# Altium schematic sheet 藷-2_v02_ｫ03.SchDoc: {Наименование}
size 420 x 297 mm; DrawnBy: Булычев; Engineer: {Инженер}; DocumentNumber: СИЭТ 21.02.110.000 Э3; SheetNumber: 3; SheetTotal: 6; Title1str: Плата управления; PageSetup: Record=PageOptions|CenterHorizontal=False|CenterVertical=False|PrintScale=0.95|XCorrection=1.00|YCorrection=1.00|PrintKind=2|BorderSize=5000000|LeftOffset=300|BottomOffset=0|Orientation=2|PaperLength=4200|PaperWidth=2970|Scale=100|PaperSource=15|PrintQuality=-1|MediaType=1|DitherType=10|PaperKind=ISO A3|PrintScaleMode=1; Title2str: (ПУ-2); EngineerName: {Инженер}; DocumentType: Схема электрическая принципиальная; DocumentType1str: {Документ}; DocumentType2str: {Документ}
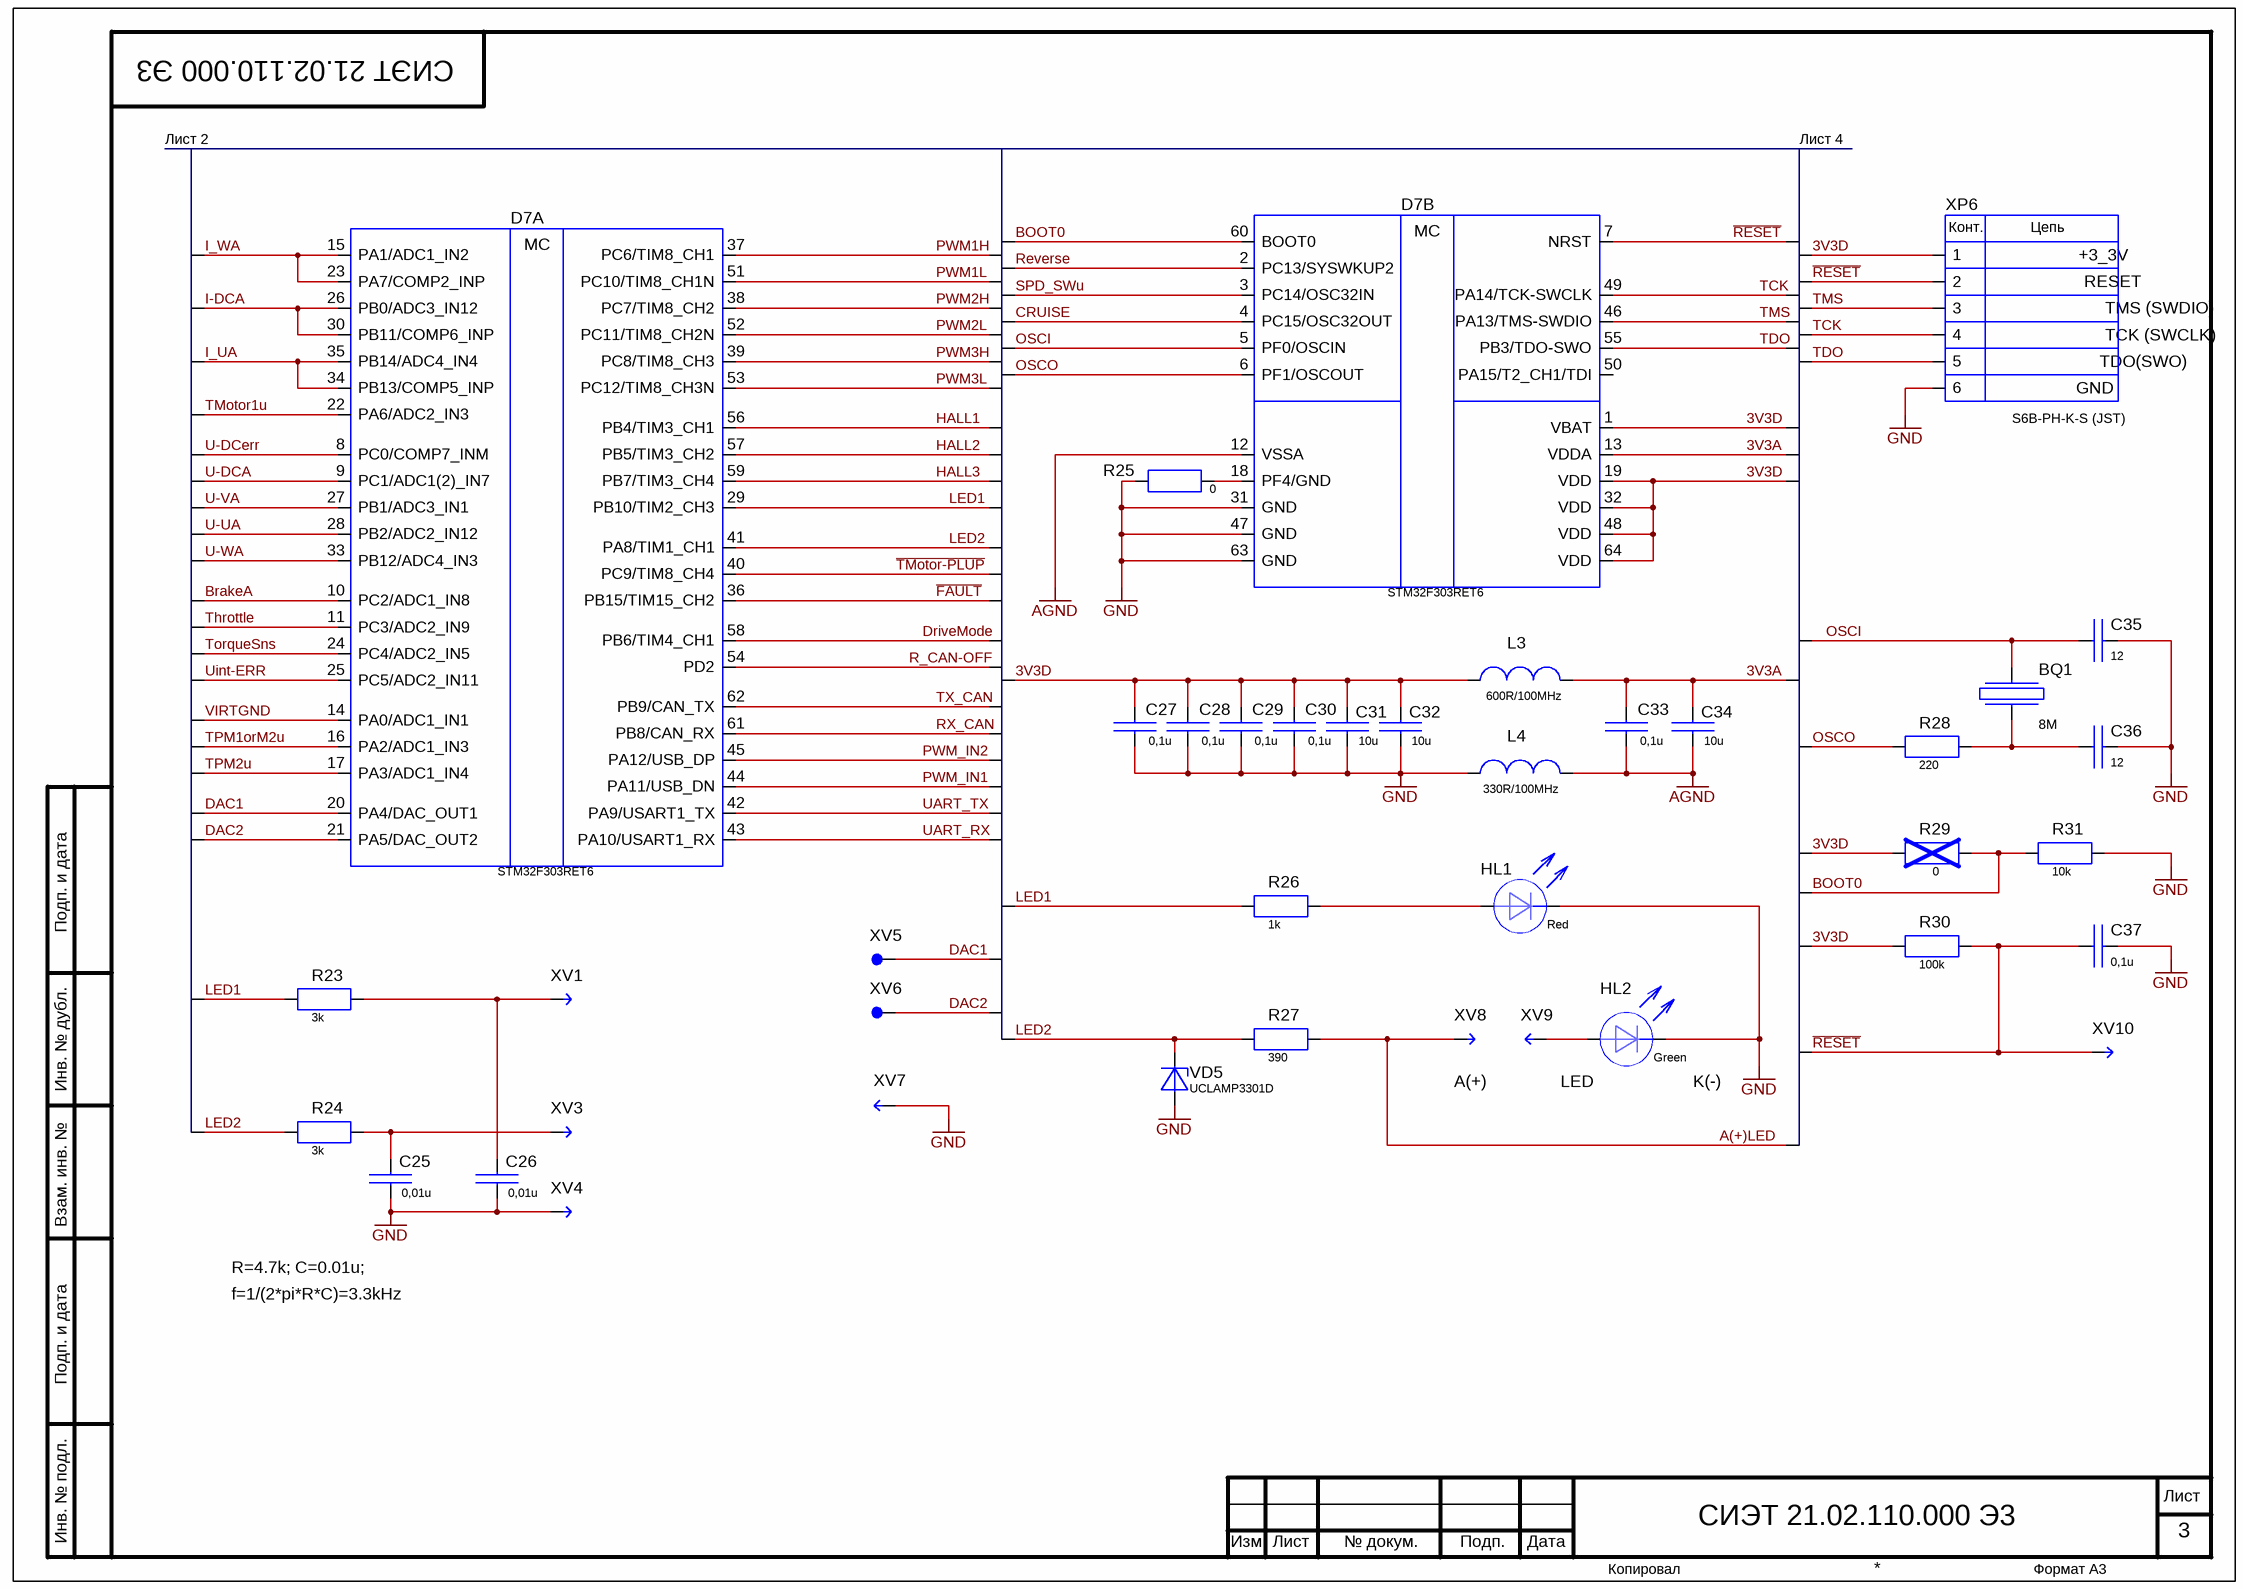
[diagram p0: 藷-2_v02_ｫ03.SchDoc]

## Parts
BQ1  value 8M  [MJ-series]  (hidden comment: MJ-8.000-12-20/20I)
C25  value 0,01u  [0603]  (hidden comment: CL10B103KB8NNNC)
C26  value 0,01u  [0603]  (hidden comment: CL10B103KB8NNNC)
C27  value 0,1u  [0603]  (hidden comment: CL10B104KB8NNNC)
C28  value 0,1u  [0603]  (hidden comment: CL10B104KB8NNNC)
C29  value 0,1u  [0603]  (hidden comment: CL10B104KB8NNNC)
C30  value 0,1u  [0603]  (hidden comment: CL10B104KB8NNNC)
C31  value 10u  [0603]  (hidden comment: CL10A106MQ8NNNC)
C32  value 10u  [0603]  (hidden comment: CL10A106MQ8NNNC)
C33  value 0,1u  [0603]  (hidden comment: CL10B104KB8NNNC)
C34  value 10u  [0603]  (hidden comment: CL10A106MQ8NNNC)
C35  value 12  [0603]  (hidden comment: CL10C120JB8NNNC)
C36  value 12  [0603]  (hidden comment: CL10C120JB8NNNC)
C37  value 0,1u  [0603]  (hidden comment: CL10B104KB8NNNC)
D7  STM32F303RET6  [LQFP-64]  (parts A,B of 2)
HL1  Color: Red  [HL0603]  (hidden comment: BL-HUE36A-AV-TRB)
HL2  Color: Green  [HL0603]  (hidden comment: BL-HGF36A-AV-TRB)
L3  Impedance@100МHz: 600R/100MHz  [BLM18]  (hidden comment: BLM18RK601SN1)
L4  Impedance@100МHz: 330R/100MHz  [BLM18]  (hidden comment: BLM18PG331SN1D)
R23  value 3k  [RC0603]  (hidden comment: RC0603FR-073KL)
R24  value 3k  [RC0603]  (hidden comment: RC0603FR-073KL)
R25  value 0  [RC0603]  (hidden comment: RC0603JR-070RL)
R26  value 1k  [RC0603]  (hidden comment: RC0603FR-071KL)
R27  value 390  [RC0603]  (hidden comment: RC0603FR-07390RL)
R28  value 220  [RC0603]  (hidden comment: RC0603FR-07220RL)
R29  value 0  [RC0603]  (hidden comment: RC0603JR-070RL)
R30  value 100k  [RC0603]  (hidden comment: RC0603FR-07100KL)
R31  value 10k  [RC0603]  (hidden comment: RC0603FR-0710KL)
VD5  UCLAMP3301D  [SOD-323]
XP6  440055-6  [440055-6]  (value not drawn)  (parts A,B,C,D,E,F,G of 7)
XV1  PLS-1  [PLS-1]  (value not drawn)
XV3  PLS-1  [PLS-1]  (value not drawn)
XV4  PLS-1  [PLS-1]  (value not drawn)
XV5  Control Point  [Control Point]  (value not drawn)
XV6  Control Point  [Control Point]  (value not drawn)
XV7  PLS-1  [PLS-1]  (value not drawn)
XV8  PLS-1  [PLS-1]  (value not drawn)
XV9  PLS-1  [PLS-1]  (value not drawn)
XV10  PLS-1  [PLS-1]  (value not drawn)

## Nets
AGND: C33.1 C34.1 D7.12(VSSA) L4.2
GND: C25.1 C26.1 C27.1 C28.1 C29.1 C30.1 C31.1 C32.1 C35.1 C36.1 C37.1 D7.31(GND) D7.47(GND) D7.63(GND) HL1.1(Катод) HL2.1(Катод) L4.1 R25.2 R31.2 VD5.2(A) XP6.6 XV4.1 XV7.1
3V3A: C33.2 C34.2 D7.13(VDDA) L3.2
3V3D: C27.2 C28.2 C29.2 C30.2 C31.2 C32.2 D7.1(VBAT) D7.19(VDD) D7.32(VDD) D7.48(VDD) D7.64(VDD) L3.1 R29.2 R30.2 XP6.1
~{FAULT}: D7.36(PB15/TIM15_CH2)
~{RESET}: C37.2 D7.7(NRST) R30.1 XP6.2 XV10.1
~{TMotor-PLUP}: D7.40(PC9/TIM8_CH4)
A(+)LED: R27.1 XV8.1
BOOT0: D7.60(BOOT0) R29.1 R31.1
BrakeA: D7.10(PC2/ADC1_IN8)
CRUISE: D7.4(PC15/OSC32OUT)
DAC1: D7.20(PA4/DAC_OUT1) XV5.1
DAC2: D7.21(PA5/DAC_OUT2) XV6.1
DriveMode: D7.58(PB6/TIM4_CH1)
HALL1: D7.56(PB4/TIM3_CH1)
HALL2: D7.57(PB5/TIM3_CH2)
HALL3: D7.59(PB7/TIM3_CH4)
I-DCA: D7.26(PB0/ADC3_IN12) D7.30(PB11/COMP6_INP)
I_UA: D7.34(PB13/COMP5_INP) D7.35(PB14/ADC4_IN4)
I_WA: D7.15(PA1/ADC1_IN2) D7.23(PA7/COMP2_INP)
LED1: D7.29(PB10/TIM2_CH3) R23.1 R26.2
LED2: D7.41(PA8/TIM1_CH1) R24.1 R27.2 VD5.1(C)
OSCI: BQ1.4 C35.2 D7.5(PF0/OSCIN)
OSCO: D7.6(PF1/OSCOUT) R28.2
PWM1H: D7.37(PC6/TIM8_CH1)
PWM1L: D7.51(PC10/TIM8_CH1N)
PWM2H: D7.38(PC7/TIM8_CH2)
PWM2L: D7.52(PC11/TIM8_CH2N)
PWM3H: D7.39(PC8/TIM8_CH3)
PWM3L: D7.53(PC12/TIM8_CH3N)
PWM_IN1: D7.44(PA11/USB_DN)
PWM_IN2: D7.45(PA12/USB_DP)
R_CAN-OFF: D7.54(PD2)
Reverse: D7.2(PC13/SYSWKUP2)
RX_CAN: D7.61(PB8/CAN_RX)
SPD_SWu: D7.3(PC14/OSC32IN)
TCK: D7.49(PA14/TCK-SWCLK) XP6.4
TDO: D7.55(PB3/TDO-SWO) XP6.5
Throttle: D7.11(PC3/ADC2_IN9)
TMotor1u: D7.22(PA6/ADC2_IN3)
TMS: D7.46(PA13/TMS-SWDIO) XP6.3
TorqueSns: D7.24(PC4/ADC2_IN5)
TPM1orM2u: D7.16(PA2/ADC1_IN3)
TPM2u: D7.17(PA3/ADC1_IN4)
TX_CAN: D7.62(PB9/CAN_TX)
U-DCA: D7.9(PC1/ADC1(2)_IN7)
U-DCerr: D7.8(PC0/COMP7_INM)
U-UA: D7.28(PB2/ADC2_IN12)
U-VA: D7.27(PB1/ADC3_IN1)
U-WA: D7.33(PB12/ADC4_IN3)
UART_RX: D7.43(PA10/USART1_RX)
UART_TX: D7.42(PA9/USART1_TX)
Uint-ERR: D7.25(PC5/ADC2_IN11)
VIRTGND: D7.14(PA0/ADC1_IN1)
NetBQ1_2: BQ1.2 C36.2 R28.1
NetC25_2: C25.2 R24.2 XV3.1
NetC26_2: C26.2 R23.2 XV1.1
NetD7_18: D7.18(PF4/GND) R25.1
NetHL1_2: HL1.2(Анод) R26.1
NetHL2_2: HL2.2(Анод) XV9.1

Not connected (* = marked no-connect by the designer): D7 50(PA15/T2_CH1/TDI)

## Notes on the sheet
- Лист 2
- Лист 4
- (near XP6) XP6
- +3_3V
- RESET
- TMS (SWDIO)
- GND
- TDO(SWO)
- TCK (SWCLK)
- (near XV8) A(+)
- LED
- (near HL2) K(-)
- R=4.7k; C=0.01u;
- f=1/(2*pi*R*C)=3.3kHz

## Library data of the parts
BQ1 = MJ-16.000-16P: Кварцевый резонатор; Pdf: Mercury MJ.pdf
C25 C26 = CL10B103KB8NNNC: 0603 - 50V - 0,01uF; Pdf: GeneralCapacitors_12022.pdf; Voltage: 50В; Type: CL10; Tolerance: ±10%; ТКЕ: X7R
C27-C30 C33 C37 = CL10B104KB8NNNC: 0603 - 50V - 0,1uF; Pdf: GeneralCapacitors_12022.pdf; Voltage: 50В; Type: CL10; Tolerance: ±10%; ТКЕ: X7R
C31 C32 C34 = CL10A225KP8NNNC: 0603, 10V, 2.2uF; Pdf: GeneralCapacitors_12022.pdf; Voltage: 6,3В; Type: CL10; Tolerance: ±10%; ТКЕ: X5R
C35 C36 = CL10C120JB8NNNC: 0603 - 50V - 12pF; Pdf: GeneralCapacitors_12022.pdf; Voltage: 50В; Type: CL10; Tolerance: ±5%; ТКЕ: NP0
D7 = STM32F303RCT6: ARM Cortex-M4 32-b MCU+FPU with 256 KB Flash, CAN, 4 ADCs, 7 comp, 4PGA; Pdf: STM32F303RC.pdf; Замена 1: STM32F303RCT7; Замена 2: STM32F303RBT6
HL1 = BL-HGF36A-AV-TRB: Surface Mount LED; Pdf: BL-HUE36A-AV-TRB.pdf; Type: BL-Hxxxxx-TRB; Исполнение: Светодиод
HL2 = BL-HGF36A-AV-TRB: Surface Mount LED; Pdf: BL-HGF36A-AV-TRB.pdf; Type: BL-Hxxxxx-TRB; Исполнение: Светодиод
L3 = BLM18AG601SN1D: EMI Suppression Filter; Корпус: 0603; Pdf: Murata BLM.pdf; DCResistance: 0.5
L4 = BLM18PG331SN1D: EMI Suppression Filter; Корпус: 0603; Pdf: Murata BLM.pdf; DCResistance: 0.15
R23 R24 R26-R28 R30 R31 = RC0603: 0603, 0.1W, Thick Film Chip Resistors; Power: 0,1 Вт; Tolerance: ±1%; Pdf: RC0603.pdf; Корпус: 0603; ТКС: ±100 ppm/K
R25 R29 = RC0603: 0603, 0.1W, Thick Film Chip Resistors; Power: 0,1 Вт; Tolerance: ±5%; Pdf: RC0603.pdf; Корпус: 0603; ТКС: ±100 ppm/K
VD5 = UCLAMP3301D: Transient Volnage Supressor Power 100 W; Pdf: UCLAMP3301D.pdf; КД: UCLAMP3301D.TCT; Замена 1: AQ4020-01FTG; Замена 2: SP4020-01FTG; Замена 3: BZT52C3V6S-TP
XP6 = 440055-6: Вилка уголовая на плату 6 контактов; Pdf: ENG_CD_440055_B4.pdf; Исполнение: Header Male Pin, Right Angle; Конт. отв. части (AWG30-24; 0,2-0,32mm): 1735801-1; Ответная часть (обжимка на провод): 440129-6; Замена 1 (Отв. часть на провод): PHR-6; Замена 1: S6B-PH-K-S (JST); Замена 2: CI0106P1HK0 (CviLux); Замена 2 (Отв. часть на провод): CI0106S1A00 (CviLux); Замена 1 (Конт. отв. части): SPH-002T-P0.5S; Замена 2 (Конт. отв. части): CI01T011PE0
XV1 XV3 XV4 XV7-XV10 = DS1021-1x1: Вилка PLS; КД: Вилка DS1021-1x1 (PLS-1)
XV5 XV6 = Control Point: Контрольная точка с отверстием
